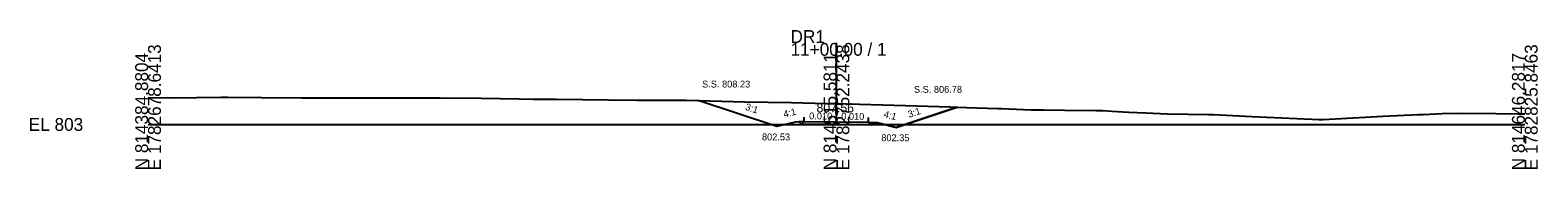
# Model space of a CAD drawing. Extents: x -26 to 303, y -10 to 2017.
# Drawn here: x -25.7 to 302.8, y 1490.3 to 1520.6 of the extents above; entities that cross this region are included whole.
import ezdxf

# ---------------------------------------------------------------- set-up
doc = ezdxf.new("R2010")
doc.units = 0
for name, color, linetype in [('Exist Cross Section Cell', 7, 'Continuous'), ('Exist XS Center Line Elevation Label', 7, 'Continuous'), ('Exist XS Ground Line', 7, 'Continuous'), ('Prop XS Ditch Slope Text', 7, 'Continuous'), ('Prop XS Ditch Standard Text', 7, 'Continuous'), ('Prop XS Dump Level', 7, 'Continuous'), ('Prop XS Earthwork Shape', 7, 'Continuous'), ('Prop XS EOT Tick Mark', 7, 'Continuous'), ('Prop XS Finish Grade', 7, 'Continuous'), ('Prop XS Finish Grade Earthwork', 7, 'Continuous'), ('Prop XS Finish Grade Pavement', 7, 'Continuous'), ('Prop XS Pvmt Edge Slope', 7, 'Continuous'), ('Prop XS SE Text', 7, 'Continuous'), ('Prop XS Side Slope Text', 7, 'Continuous'), ('Prop XS SS Elevation Text', 7, 'Continuous'), ('Prop XS Subgrade Earthwork', 7, 'Continuous')]:
    doc.layers.add(name, color=color, linetype=linetype)

msp = doc.modelspace()

# ---------------------------------------------------------------- linework, layer by layer
at = {"layer": 'Exist Cross Section Cell'}
for p, q in [((150, 1500), (150, 1517.79)), ((0, 1500), (150, 1500)), ((150, 1500), (300, 1500))]:
    msp.add_line(p, q, dxfattribs=at)
at = {"layer": 'Exist XS Ground Line'}
for p, q in [((0, 1505.87), (5.28, 1505.84)), ((5.28, 1505.84), (15.84, 1505.93)), ((15.84, 1505.93), (17.35, 1505.93)), ((17.35, 1505.93), (24.71, 1505.9)), ((24.71, 1505.9), (33.46, 1505.82)), ((33.46, 1505.82), (34.96, 1505.8)), ((34.96, 1505.8), (40.96, 1505.81)), ((40.96, 1505.81), (49.3, 1505.84)), ((49.3, 1505.84), (50.72, 1505.84)), ((50.72, 1505.84), (53.74, 1505.82)), ((53.74, 1505.82), (63.64, 1505.84)), ((63.64, 1505.84), (72.59, 1505.73)), ((72.59, 1505.73), (80.87, 1505.57)), ((80.87, 1505.57), (83.94, 1505.55)), ((83.94, 1505.55), (89, 1505.55)), ((89, 1505.55), (100.34, 1505.4)), ((100.34, 1505.4), (106.51, 1505.33)), ((106.51, 1505.33), (116.69, 1505.31)), ((116.69, 1505.31), (117.22, 1505.3)), ((117.22, 1505.3), (130.02, 1504.95)), ((130.02, 1504.95), (135.1, 1504.86)), ((135.1, 1504.86), (140.2, 1504.77)), ((140.2, 1504.77), (147.8, 1504.6)), ((147.8, 1504.6), (150, 1504.56)), ((150, 1504.56), (150.55, 1504.54)), ((150.55, 1504.54), (152.05, 1504.5)), ((152.05, 1504.5), (155.05, 1504.43)), ((155.05, 1504.43), (165.05, 1504.14)), ((165.05, 1504.14), (174.69, 1503.82)), ((174.69, 1503.82), (175.08, 1503.81)), ((175.08, 1503.81), (176.02, 1503.79)), ((176.02, 1503.79), (182.94, 1503.57)), ((182.94, 1503.57), (185.2, 1503.47)), ((185.2, 1503.47), (185.96, 1503.46)), ((185.96, 1503.46), (192.34, 1503.22)), ((192.34, 1503.22), (195.11, 1503.23)), ((195.11, 1503.23), (199.71, 1503.12)), ((199.71, 1503.12), (206.53, 1503.04)), ((206.53, 1503.04), (208.03, 1503.02)), ((208.03, 1503.02), (210.03, 1502.91)), ((210.03, 1502.91), (213.7, 1502.65)), ((213.7, 1502.65), (217.44, 1502.51)), ((217.44, 1502.51), (222.09, 1502.35)), ((222.09, 1502.35), (231.11, 1502.2)), ((231.11, 1502.2), (231.43, 1502.19)), ((231.43, 1502.19), (232.14, 1502.17)), ((232.14, 1502.17), (240.52, 1501.74)), ((240.52, 1501.74), (253.62, 1501.18)), ((256.05, 1501.07), (265.24, 1501.58)), ((265.24, 1501.58), (269.04, 1501.8)), ((269.04, 1501.8), (276.84, 1502.18)), ((276.84, 1502.18), (277.84, 1502.21)), ((277.84, 1502.21), (282.01, 1502.41)), ((282.01, 1502.41), (286.54, 1502.5)), ((286.54, 1502.5), (293.71, 1502.41)), ((293.71, 1502.41), (298.58, 1502.34)), ((298.58, 1502.34), (300, 1502.32)), ((253.62, 1501.18), (255.13, 1501.11)), ((255.13, 1501.11), (256.05, 1501.07))]:
    msp.add_line(p, q, dxfattribs=at)
at = {"layer": 'Prop XS Dump Level'}
for p, q in [((143, 1500.63), (150, 1500.56)), ((150, 1500.56), (157, 1500.49))]:
    msp.add_line(p, q, dxfattribs=at)
at = {"layer": 'Prop XS Earthwork Shape'}
msp.add_lwpolyline([(119.89, 1505.23), (130.02, 1504.95), (135.1, 1504.86), (140.2, 1504.77), (147.8, 1504.6), (150, 1504.56), (150.55, 1504.54), (152.05, 1504.5), (155.05, 1504.43), (165.05, 1504.14), (174.69, 1503.82), (175.08, 1503.81), (176.02, 1503.79), (176.3, 1503.78), (163, 1499.35), (159, 1500.35), (158.1, 1500.41), (157.59, 1499.9), (149.99, 1499.97), (142.42, 1500.05), (141.9, 1500.57), (141, 1500.53), (137, 1499.53)], close=True, dxfattribs=at)
at = {"layer": 'Prop XS EOT Tick Mark'}
for p, q in [((143, 1500.63), (143, 1501.63)), ((157, 1500.49), (157, 1501.49))]:
    msp.add_line(p, q, dxfattribs=at)
at = {"layer": 'Prop XS Finish Grade'}
for p, q in [((143, 1500.63), (141.9, 1500.57)), ((157, 1500.49), (158.1, 1500.41))]:
    msp.add_line(p, q, dxfattribs=at)
at = {"layer": 'Prop XS Finish Grade Earthwork'}
for p, q in [((137, 1499.53), (119.89, 1505.23)), ((163, 1499.35), (176.3, 1503.78)), ((141, 1500.53), (137, 1499.53)), ((141.9, 1500.57), (141, 1500.53)), ((158.1, 1500.41), (159, 1500.35)), ((159, 1500.35), (163, 1499.35))]:
    msp.add_line(p, q, dxfattribs=at)
at = {"layer": 'Prop XS Finish Grade Pavement'}
for p, q in [((143, 1500.63), (150, 1500.56)), ((150, 1500.56), (157, 1500.49))]:
    msp.add_line(p, q, dxfattribs=at)
at = {"layer": 'Prop XS Pvmt Edge Slope'}
for p, q in [((143, 1500.63), (142.42, 1500.05)), ((157, 1500.49), (157.59, 1499.9))]:
    msp.add_line(p, q, dxfattribs=at)
at = {"layer": 'Prop XS Subgrade Earthwork'}
for p, q in [((142.42, 1500.05), (141.9, 1500.57)), ((142.42, 1500.05), (149.99, 1499.97)), ((149.99, 1499.97), (157.59, 1499.9)), ((157.59, 1499.9), (158.1, 1500.41))]:
    msp.add_line(p, q, dxfattribs=at)

# ---------------------------------------------------------------- texts
at = {"layer": 'Exist Cross Section Cell'}
for s, p in [('11+00.00 / 1', (140, 1514.99)), ('DR1', (140, 1517.79)), ('EL 803', (-26, 1498.6))]:
    msp.add_text(s, height=2.8, dxfattribs=at).set_placement(p)
for s, p in [('N 814384.8804', (0, 1490)), ('E 1782678.6413', (2.8, 1490)), ('N 814515.5811', (150, 1490)), ('E 1782752.2438', (152.8, 1490)), ('N 814646.2817', (300, 1490)), ('E 1782825.8463', (302.8, 1490))]:
    msp.add_text(s, height=2.8, rotation=90, dxfattribs=at).set_placement(p)
at = {"layer": 'Exist XS Center Line Elevation Label'}
msp.add_text('807.56', height=2, dxfattribs=at).set_placement((145.65, 1502.65))
at = {"layer": 'Prop XS Ditch Slope Text'}
for rotation, p in [(14.0362, (138.64, 1501.48)), (345.9638, (160.19, 1501.6))]:
    msp.add_text('4:1', height=1.5, rotation=rotation, dxfattribs=at).set_placement(p)
at = {"layer": 'Prop XS Ditch Standard Text'}
for s, p in [('802.53', (133.77, 1496.53)), ('802.35', (159.77, 1496.35))]:
    msp.add_text(s, height=1.5, dxfattribs=at).set_placement(p)
at = {"layer": 'Prop XS Dump Level'}
for p in [(141, 1500.49), (159, 1500.31)]:
    msp.add_text('Case1', height=0.04, dxfattribs=at).set_placement(p)
at = {"layer": 'Prop XS SE Text'}
for p in [(144.05, 1501.12), (151.05, 1501.05)]:
    msp.add_text('0.010', height=1.5, rotation=359.4271, dxfattribs=at).set_placement(p)
at = {"layer": 'Prop XS Side Slope Text'}
for rotation, p in [(341.5651, (130.01, 1503.25)), (18.4349, (165.86, 1501.44))]:
    msp.add_text('3:1', height=1.5, rotation=rotation, dxfattribs=at).set_placement(p)
at = {"layer": 'Prop XS SS Elevation Text'}
for s, p in [('S.S. 808.23', (120.73, 1508.07)), ('S.S. 806.78', (166.89, 1506.91))]:
    msp.add_text(s, height=1.5, dxfattribs=at).set_placement(p)

doc.saveas('drawing.dxf')
